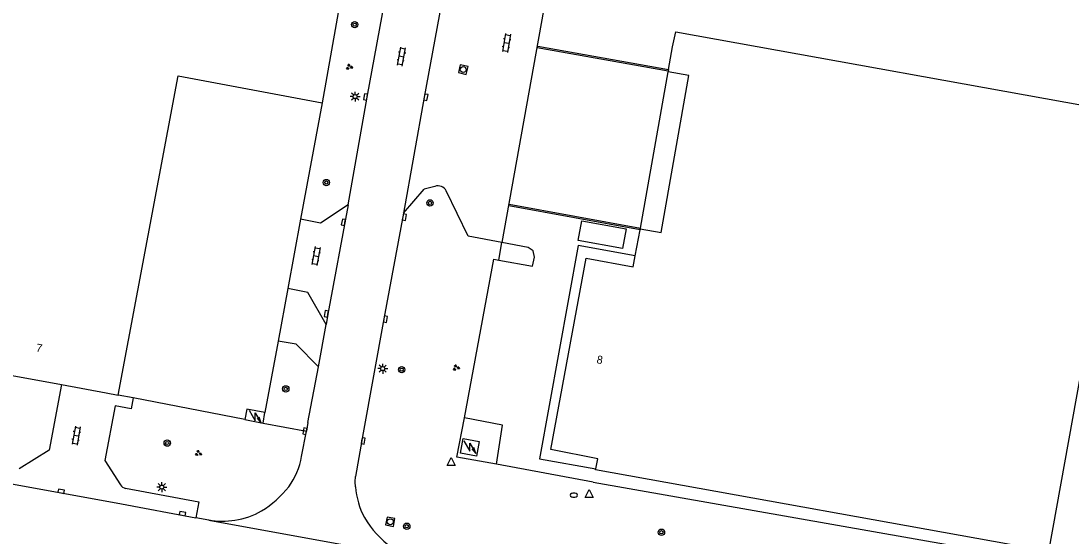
# Model space of a CAD drawing. Extents: x 130998 to 133001, y 398999 to 403002.
# Drawn here: x 132332.6 to 132463.8, y 399252 to 399316.5 of the extents above; entities that cross this region are included whole.
import ezdxf

# ---------------------------------------------------------------- set-up
doc = ezdxf.new("R2010")
doc.units = 0
for name, color, linetype in [('gg-afsc-hekwerk', 7, 'Continuous'), ('gg-afsc-muur', 7, 'Continuous'), ('gg-anno-huisnummerreeks BGT', 7, 'Continuous'), ('gg-bbg-hoofdgebouw', 7, 'Continuous'), ('gg-bbg-lage trafo', 7, 'Continuous'), ('gg-bbg-luifel en loopbrug', 7, 'Continuous'), ('gg-bbg-onder overbouw', 7, 'Continuous'), ('gg-bbg-pand overbouw', 7, 'Continuous'), ('gg-knt-verharding', 7, 'Continuous'), ('gg-knt-verharding nz', 7, 'Continuous'), ('gt-grn-groengrens', 7, 'Continuous'), ('gt-grn-vlakafsluiter', 7, 'Continuous'), ('gt-grn-weggrens', 7, 'Continuous'), ('gt-symb-boom', 7, 'Continuous'), ('gt-symb-brandkraan', 7, 'Continuous'), ('gt-symb-groenvak', 7, 'Continuous'), ('gt-symb-klinker verharding', 7, 'Continuous'), ('gt-symb-kolk', 7, 'Continuous'), ('gt-symb-lichtmast', 7, 'Continuous'), ('gt-symb-rioolschacht', 7, 'Continuous'), ('gt-symb-trafo symbool', 7, 'Continuous'), ('gt-symb-waterafsluiter', 7, 'Continuous')]:
    doc.layers.add(name, color=color, linetype=linetype)

# ---------------------------------------------------------------- blocks, each defined once
blk = doc.blocks.new('gt0-WAFSL')
at = {"layer": 'gt-symb-waterafsluiter'}
for p, q in [((-0.5, -0.33), (0, 0.67)), ((0, 0.67), (0.5, -0.33)), ((0.5, -0.33), (-0.5, -0.33))]:
    blk.add_line(p, q, dxfattribs=at)
blk = doc.blocks.new('gt0-HSP')
at = {"layer": 'gt-symb-trafo symbool'}
for points in [[(0.77, 0.75), (-0.53, 0), (0.47, 0), (-0.83, -0.75)], [(-0.22, -0.24), (-0.83, -0.75), (-0.08, -0.48)]]:
    blk.add_lwpolyline(points, dxfattribs=at)
blk = doc.blocks.new('gt0-GRVAK')
at = {"layer": 'gt-symb-groenvak'}
for p, q in [((-0.11, 0.19), (-0.23, 0.24)), ((-0.18, 0.15), (0.09, 0.15)), ((-0.09, 0.21), (-0.16, 0.32)), ((-0.05, 0.21), (-0.05, 0.39)), ((0, 0.21), (0.06, 0.32)), ((0.01, 0.19), (0.13, 0.24)), ((0.26, -0.05), (0.2, 0.06)), ((0.3, -0.05), (0.3, 0.13)), ((0.35, -0.05), (0.41, 0.06)), ((-0.24, -0.23), (-0.36, -0.18)), ((-0.32, -0.26), (-0.05, -0.26)), ((-0.23, -0.21), (-0.29, -0.09)), ((-0.18, -0.2), (-0.18, -0.02)), ((-0.14, -0.21), (-0.07, -0.09)), ((-0.12, -0.23), (0, -0.18)), ((0.24, -0.07), (0.12, -0.02)), ((0.17, -0.11), (0.44, -0.11)), ((0.37, -0.07), (0.49, -0.02))]:
    blk.add_line(p, q, dxfattribs=at)
blk = doc.blocks.new('gt0-BOOM')
at = {"layer": 'gt-symb-boom'}
for radius in [0.4, 0.2]:
    blk.add_circle((0, 0), radius, dxfattribs=at)
blk = doc.blocks.new('gt0-RS')
at = {"layer": 'gt-symb-rioolschacht'}
blk.add_lwpolyline([(-0.5, -0.5), (0.5, -0.5), (0.5, 0.5), (-0.5, 0.5)], close=True, dxfattribs=at)
blk.add_circle((0, 0), 0.375, dxfattribs=at)
blk = doc.blocks.new('gt0-KL1')
at = {"layer": 'gt-symb-klinker verharding'}
for p, q in [((-1.15, 0.3), (1.15, 0.3)), ((-1, -0.3), (-1, 0.3)), ((-0.5, 0.3), (-0.5, 0.45)), ((0, -0.3), (0, 0.3)), ((0.5, 0.3), (0.5, 0.45)), ((1, -0.3), (1, 0.3)), ((-1.15, -0.3), (1.15, -0.3)), ((-0.5, -0.45), (-0.5, -0.3)), ((0.5, -0.45), (0.5, -0.3))]:
    blk.add_line(p, q, dxfattribs=at)
blk = doc.blocks.new('gt0-KOLK')
at = {"layer": 'gt-symb-kolk'}
blk.add_lwpolyline([(0, 0), (0.37, 0), (0.37, 0.4), (-0.38, 0.4), (-0.38, 0), (0, 0)], dxfattribs=at)
blk = doc.blocks.new('gt0-LMAST')
at = {"layer": 'gt-symb-lichtmast'}
for p, q in [((-0.18, 0.17), (-0.45, 0.44)), ((-0.01, 0.25), (-0.01, 0.62)), ((0.17, 0.17), (0.44, 0.44)), ((-0.26, 0), (-0.63, 0)), ((-0.18, -0.18), (-0.45, -0.45)), ((-0.01, -0.25), (-0.01, -0.63)), ((0.44, -0.45), (0.17, -0.18)), ((0.24, 0), (0.62, 0))]:
    blk.add_line(p, q, dxfattribs=at)
blk.add_circle((-0.01, 0), 0.25, dxfattribs=at)
blk = doc.blocks.new('gt0-BR')
at = {"layer": 'gt-symb-brandkraan'}
for centre, radius, start, end in [((-0.24, 0), 0.206, 107.5669, 252.4331), ((0.6, -2.66), 3, 106.892, 107.5669), ((0, -0.69), 0.938, 73.108, 106.892), ((-0.6, -2.66), 3, 72.4331, 73.108), ((0.24, 0), 0.206, 287.567, 72.4331), ((0.6, 2.66), 3, 252.4331, 253.108), ((0, 0.69), 0.938, 253.108, 286.8921), ((-0.6, 2.66), 3, 286.8921, 287.567)]:
    blk.add_arc(centre, radius, start, end, dxfattribs=at)

msp = doc.modelspace()

# ---------------------------------------------------------------- linework, layer by layer
at = {"layer": 'gg-afsc-hekwerk'}
for p, q in [((132370.2, 399306.24), (132367.51, 399291.66)), ((132367.51, 399291.66), (132365.91, 399282.98)), ((132365.91, 399282.98), (132364.7, 399276.41)), ((132364.7, 399276.41), (132363.05, 399267.47)), ((132346.59, 399269.29), (132344.7, 399269.66)), ((132360.53, 399266.58), (132346.59, 399269.29))]:
    msp.add_line(p, q, dxfattribs=at)
at = {"layer": 'gg-afsc-muur'}
for points in [[(132413.44, 399310.18), (132397.09, 399313.12), (132397.16, 399313.33), (132413.48, 399310.38)], [(132409.93, 399290.34), (132393.53, 399293.34), (132393.57, 399293.56), (132409.97, 399290.56)]]:
    msp.add_lwpolyline(points, dxfattribs=at)
at = {"layer": 'gg-bbg-hoofdgebouw'}
for p, q in [((132374.47, 399330.19), (132370.2, 399306.24)), ((132413.44, 399310.18), (132413.43, 399310.1)), ((132413.48, 399310.38), (132413.44, 399310.18)), ((132409.34, 399287.09), (132409.93, 399290.34)), ((132409.96, 399290.47), (132409.93, 399290.34)), ((132323.46, 399273.57), (132337.64, 399270.96)), ((132362.81, 399266.15), (132363.05, 399267.47)), ((132360.53, 399266.58), (132362.81, 399266.15))]:
    msp.add_line(p, q, dxfattribs=at)
for points in [[(132413.48, 399310.38), (132413.99, 399313.23), (132414.42, 399315.09), (132470.77, 399304.91), (132470.43, 399303.03), (132470.54, 399303), (132460.98, 399250.08), (132460.81, 399250.11)], [(132344.7, 399269.66), (132352.2, 399309.62), (132370.2, 399306.24)], [(132404.4, 399260.42), (132404.65, 399261.67), (132398.8, 399262.84), (132403.18, 399286.8), (132409.09, 399285.72), (132409.34, 399287.09)], [(132337.64, 399270.96), (132343.22, 399269.93), (132344.7, 399269.66)], [(132363.05, 399267.47), (132360.77, 399267.9), (132360.53, 399266.58)], [(132460.81, 399250.11), (132404.38, 399260.32), (132404.4, 399260.42)]]:
    msp.add_lwpolyline(points, dxfattribs=at)
at = {"layer": 'gg-bbg-lage trafo'}
msp.add_lwpolyline([(132389.84, 399263.84), (132389.51, 399262.02), (132387.48, 399262.38), (132387.81, 399264.21), (132389.84, 399263.84)], dxfattribs=at)
at = {"layer": 'gg-bbg-luifel en loopbrug'}
for points in [[(132402.65, 399291.47), (132408.19, 399290.47), (132407.74, 399287.99), (132402.2, 399288.99), (132402.65, 399291.47)], [(132409.34, 399287.09), (132402.19, 399288.39), (132397.36, 399261.69), (132404.4, 399260.42)]]:
    msp.add_lwpolyline(points, dxfattribs=at)
at = {"layer": 'gg-bbg-onder overbouw'}
msp.add_lwpolyline([(132409.96, 399290.47), (132412.56, 399289.99), (132416.04, 399309.64), (132413.43, 399310.1)], dxfattribs=at)
at = {"layer": 'gg-bbg-pand overbouw'}
for p, q in [((132409.97, 399290.56), (132413.43, 399310.1)), ((132409.96, 399290.47), (132409.97, 399290.56))]:
    msp.add_line(p, q, dxfattribs=at)
at = {"layer": 'gg-knt-verharding'}
for p, q in [((132399.52, 399326.93), (132392.67, 399288.74)), ((132380.37, 399292.4), (132382.95, 399295.4)), ((132384.3, 399295.77), (132382.95, 399295.4)), ((132369.73, 399273.18), (132370.71, 399278.47)), ((132368.43, 399266.21), (132369.73, 399273.18)), ((132368.43, 399266.21), (132368.24, 399265.15)), ((132367.64, 399261.96), (132368.24, 399265.15)), ((132375.32, 399264.95), (132374.35, 399259.47)), ((132404.07, 399258.77), (132391.98, 399260.99)), ((132404.07, 399258.77), (132460.6, 399248.82)), ((132345.63, 399257.99), (132354.78, 399256.29)), ((132354.78, 399256.29), (132354.41, 399254.31)), ((132356.02, 399254.02), (132354.41, 399254.31))]:
    msp.add_line(p, q, dxfattribs=at)
for points in [[(132373.46, 399293.44), (132375.82, 399306.93), (132379.57, 399327.38)], [(132392.67, 399288.74), (132388.44, 399289.53), (132385.72, 399295.22)], [(132373.46, 399293.44), (132369.98, 399291.16), (132367.51, 399291.66)], [(132380.37, 399292.4), (132377.92, 399279.18), (132375.32, 399264.95)], [(132392.27, 399286.54), (132396.49, 399285.78), (132396.75, 399286.93), (132396.58, 399287.71), (132395.96, 399288.12), (132392.67, 399288.74)], [(132387.98, 399266.79), (132391.64, 399286.66), (132392.27, 399286.54)], [(132370.71, 399278.47), (132368.43, 399282.51), (132365.91, 399282.98)], [(132337.64, 399270.96), (132336.08, 399262.77), (132332.32, 399260.41)], [(132346.59, 399269.29), (132346.34, 399267.94), (132344.32, 399268.3), (132343.05, 399261.48), (132344.99, 399258.41)], [(132391.98, 399260.99), (132392.76, 399265.87), (132387.98, 399266.79)], [(132374.37, 399258.16), (132374.33, 399258.81), (132374.35, 399259.47)]]:
    msp.add_lwpolyline(points, dxfattribs=at)
for centre, radius, start, end in [((132384.67, 399294.62), 1.21, 29.7258, 107.929), ((132358.33, 399263.74), 9.48, 324.1865, 349.1409), ((132345.79, 399258.92), 0.952, 212.5037, 260.0333), ((132356.41, 399265.55), 12.1, 300.9715, 322.5498), ((132384.43, 399258.99), 10.1, 184.7474, 207.5224), ((132358.04, 399262.93), 9.01, 278.0823, 300.7043), ((132386.5, 399260.97), 12.87, 211.096, 233.9222), ((132357.72, 399263.69), 9.81, 260.0664, 279.3047)]:
    msp.add_arc(centre, radius, start, end, dxfattribs=at)
at = {"layer": 'gg-knt-verharding nz'}
for points in [[(132387.63, 399332.5), (132385.6, 399321.46), (132382.97, 399306.95), (132380.37, 399292.4)], [(132373.46, 399293.44), (132370.92, 399279.78), (132370.71, 399278.47)], [(132329.73, 399258.83), (132345.13, 399256.04), (132354.41, 399254.31)]]:
    msp.add_lwpolyline(points, dxfattribs=at)
at = {"layer": 'gt-grn-groengrens'}
msp.add_line((132362.81, 399266.15), (132368.24, 399265.15), dxfattribs=at)
for points in [[(132369.73, 399273.18), (132366.96, 399276.01), (132364.7, 399276.41)], [(132391.98, 399260.99), (132387.04, 399261.87), (132387.98, 399266.79)]]:
    msp.add_lwpolyline(points, dxfattribs=at)
at = {"layer": 'gt-grn-vlakafsluiter'}
msp.add_line((132392.27, 399286.54), (132392.67, 399288.74), dxfattribs=at)
at = {"layer": 'gt-grn-weggrens'}
msp.add_line((132356.02, 399254.02), (132381.91, 399249.27), dxfattribs=at)

# ---------------------------------------------------------------- block references
at = {"layer": 'gt-symb-boom'}
for p in [(132374.27, 399316.01), (132370.72, 399296.25), (132383.68, 399293.7), (132380.14, 399272.83), (132365.65, 399270.43), (132350.84, 399263.65), (132380.78, 399253.24), (132412.61, 399252.49)]:
    msp.add_blockref('gt0-BOOM', p, dxfattribs=at)
at = {"layer": 'gt-symb-brandkraan'}
msp.add_blockref('gt0-BR', (132401.66, 399257.13), dxfattribs=at)
at = {"layer": 'gt-symb-groenvak'}
for p in [(132373.58, 399310.72), (132386.94, 399273.08)]:
    msp.add_blockref('gt0-GRVAK', p, dxfattribs=at)
at = {"layer": 'gt-symb-groenvak', "rotation": -9.905079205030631}
msp.add_blockref('gt0-GRVAK', (132354.72, 399262.37), dxfattribs=at)
at = {"layer": 'gt-symb-klinker verharding'}
for p, rotation in [((132393.24, 399313.72), -99.26452398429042), ((132380.11, 399312.01), 79.80279442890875), ((132369.43, 399287.06), -100.48938981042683), ((132339.46, 399264.59), -99.44347491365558)]:
    msp.add_blockref('gt0-KL1', p, dxfattribs=dict(at, rotation=rotation))
at = {"layer": 'gt-symb-kolk'}
for p, rotation in [((132375.82, 399306.93), 79.45426563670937), ((132382.97, 399306.95), -100.25359802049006), ((132380.28, 399291.94), -100.60205829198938), ((132373.05, 399291.24), 79.39794170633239), ((132370.92, 399279.78), 79.45426563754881), ((132377.92, 399279.18), -100.30997039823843), ((132368.23, 399265.11), 79.45426563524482), ((132375.13, 399263.95), -100.36632260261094), ((132337.55, 399257.42), -10.309970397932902), ((132352.72, 399254.63), -10.602058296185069)]:
    msp.add_blockref('gt0-KOLK', p, dxfattribs=dict(at, rotation=rotation))
at = {"layer": 'gt-symb-lichtmast'}
for p in [(132374.33, 399307), (132377.78, 399272.96), (132350.17, 399258.14)]:
    msp.add_blockref('gt0-LMAST', p, dxfattribs=at)
at = {"layer": 'gt-symb-rioolschacht'}
for p, rotation in [((132387.83, 399310.39), -103.24380202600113), ((132378.72, 399253.8), 79.56697526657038)]:
    msp.add_blockref('gt0-RS', p, dxfattribs=dict(at, rotation=rotation))
at = {"layer": 'gt-symb-trafo symbool', "rotation": 90}
for p in [(132361.83, 399266.98), (132388.67, 399263.16)]:
    msp.add_blockref('gt0-HSP', p, dxfattribs=at)
at = {"layer": 'gt-symb-waterafsluiter'}
for p in [(132386.32, 399261.16), (132403.58, 399257.15)]:
    msp.add_blockref('gt0-WAFSL', p, dxfattribs=at)

# ---------------------------------------------------------------- texts
at = {"layer": 'gg-anno-huisnummerreeks BGT'}
for s, p in [('7', (132334.38, 399275.12)), ('8', (132404.45, 399273.65))]:
    msp.add_text(s, height=1, rotation=349.6, dxfattribs=at).set_placement(p)

doc.saveas('drawing.dxf')
